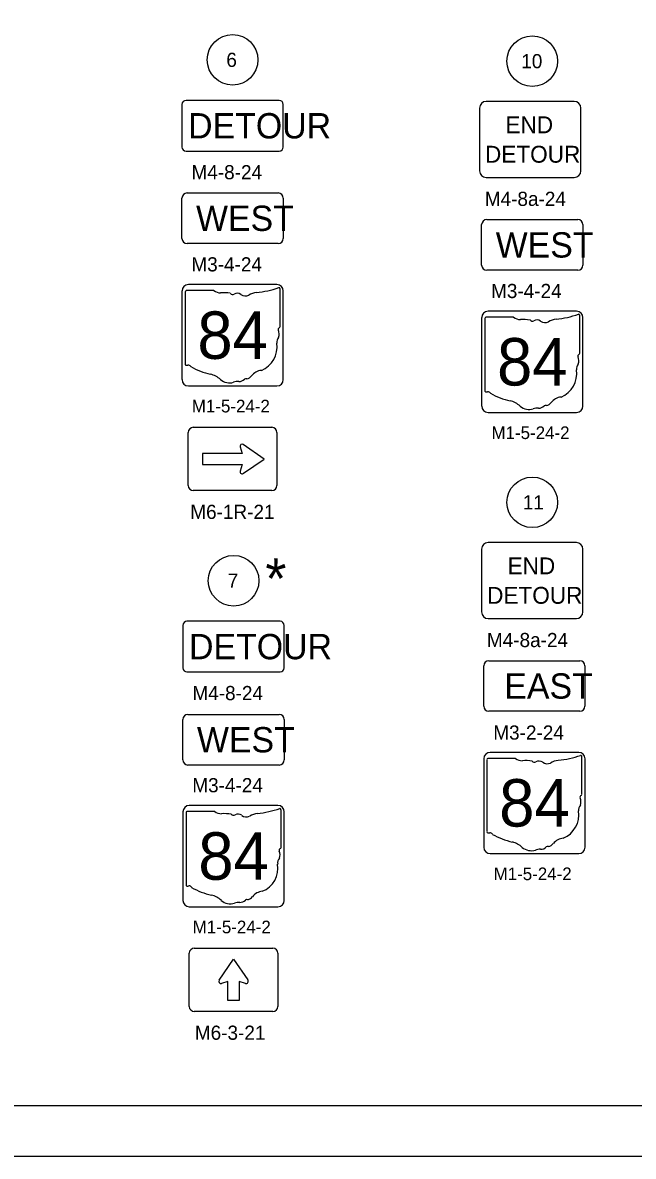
# Model space of a CAD drawing. Extents: x 0 to 54.8, y 0 to 22.
# Drawn here: x 21.94 to 27.97, y 0 to 11.2 of the extents above; entities that cross this region are included whole.
import ezdxf

# ---------------------------------------------------------------- set-up
doc = ezdxf.new("R2010")
doc.units = 0
for name, color, linetype in [('GM_X_County', 7, 'Continuous'), ('GM_X_County_Road', 7, 'Continuous'), ('GM_X_Minor_River_Text', 7, 'Continuous'), ('GM_X_Township', 7, 'Continuous')]:
    doc.layers.add(name, color=color, linetype=linetype)

msp = doc.modelspace()

# ---------------------------------------------------------------- linework, layer by layer
at = {"layer": 'GM_X_County'}
msp.add_lwpolyline([(0, 0), (34, 0), (34, 22), (0, 22)], close=True, dxfattribs=at)
at = {"layer": 'GM_X_County_Road'}
for centre in [(24.014, 10.831), (26.973, 10.818), (26.973, 6.46), (24.024, 5.686)]:
    msp.add_circle(centre, 0.25, dxfattribs=at)
at = {"layer": 'GM_X_Minor_River_Text'}
for p, q in [((23.514, 9.066), (23.514, 9.466)), ((23.564, 9.516), (24.464, 9.516)), ((24.514, 9.466), (24.514, 9.066)), ((26.473, 8.803), (26.473, 9.203)), ((26.523, 9.253), (27.423, 9.253)), ((27.473, 9.203), (27.473, 8.803)), ((24.464, 9.016), (23.564, 9.016)), ((27.423, 8.753), (26.523, 8.753)), ((23.545, 8.539), (23.545, 7.827)), ((23.829, 8.551), (23.554, 8.551)), ((24.482, 8.196), (24.482, 8.569)), ((26.788, 8.288), (26.513, 8.288)), ((27.441, 7.933), (27.441, 8.306)), ((24.482, 8.196), (24.482, 8.196)), ((26.504, 8.276), (26.504, 7.564)), ((27.441, 7.933), (27.441, 7.933)), ((23.626, 7.201), (24.401, 7.201)), ((23.576, 6.626), (23.576, 7.151)), ((24.451, 7.151), (24.451, 6.626)), ((24.108, 6.943), (23.717, 6.943)), ((23.717, 6.943), (23.717, 6.834)), ((24.088, 7.007), (24.108, 6.943)), ((24.326, 6.888), (24.119, 7.03)), ((23.717, 6.834), (24.108, 6.834)), ((24.108, 6.834), (24.088, 6.769)), ((24.122, 6.749), (24.326, 6.888)), ((24.401, 6.576), (23.626, 6.576)), ((26.493, 4.446), (26.493, 4.846)), ((26.543, 4.896), (27.443, 4.896)), ((27.493, 4.846), (27.493, 4.446)), ((27.443, 4.396), (26.543, 4.396)), ((23.523, 3.915), (23.523, 4.315)), ((23.573, 4.365), (24.473, 4.365)), ((24.523, 4.315), (24.523, 3.915)), ((26.808, 3.93), (26.534, 3.93)), ((27.462, 3.576), (27.462, 3.948)), ((24.473, 3.865), (23.573, 3.865)), ((26.525, 3.918), (26.525, 3.207)), ((27.462, 3.576), (27.462, 3.576)), ((23.554, 3.394), (23.554, 2.682)), ((23.838, 3.406), (23.563, 3.406)), ((24.492, 3.051), (24.492, 3.424)), ((24.492, 3.051), (24.492, 3.051)), ((23.636, 2.056), (24.411, 2.056)), ((23.586, 1.481), (23.586, 2.006)), ((23.881, 1.739), (24.023, 1.946)), ((24.023, 1.946), (24.163, 1.742)), ((24.461, 2.006), (24.461, 1.481)), ((23.968, 1.728), (23.904, 1.708)), ((23.968, 1.54), (23.968, 1.728)), ((24.142, 1.708), (24.078, 1.728)), ((24.078, 1.728), (24.078, 1.54)), ((24.078, 1.54), (23.968, 1.54)), ((24.411, 1.431), (23.636, 1.431))]:
    msp.add_line(p, q, dxfattribs=at)
for points in [[(24.474, 10.43), (23.554, 10.43)], [(27.388, 10.42), (26.518, 10.42)], [(23.514, 10.39), (23.514, 9.97)], [(24.514, 9.97), (24.514, 10.39)], [(26.453, 10.355), (26.453, 9.735)], [(27.453, 9.735), (27.453, 10.355)], [(23.554, 9.93), (24.474, 9.93)], [(26.518, 9.67), (27.388, 9.67)], [(23.514, 8.548), (23.514, 7.673)], [(24.452, 8.611), (23.577, 8.611)], [(24.514, 7.673), (24.514, 8.548)], [(27.411, 8.348), (26.536, 8.348)], [(26.473, 8.285), (26.473, 7.41)], [(27.473, 7.41), (27.473, 8.285)], [(23.577, 7.611), (24.452, 7.611)], [(26.536, 7.348), (27.411, 7.348)], [(27.408, 6.062), (26.538, 6.062)], [(26.473, 5.997), (26.473, 5.377)], [(27.473, 5.377), (27.473, 5.997)], [(24.483, 5.285), (23.563, 5.285)], [(26.538, 5.312), (27.408, 5.312)], [(23.523, 5.245), (23.523, 4.825)], [(24.523, 4.825), (24.523, 5.245)], [(23.563, 4.785), (24.483, 4.785)], [(26.494, 3.928), (26.494, 3.053)], [(27.432, 3.99), (26.557, 3.99)], [(27.494, 3.053), (27.494, 3.928)], [(23.524, 3.403), (23.524, 2.528)], [(24.461, 3.466), (23.586, 3.466)], [(24.524, 2.528), (24.524, 3.403)], [(26.557, 2.99), (27.432, 2.99)], [(23.586, 2.466), (24.461, 2.466)]]:
    msp.add_lwpolyline(points, dxfattribs=at)
for centre, radius, start, end in [((23.554, 10.39), 0.04, 90, 180), ((24.474, 10.39), 0.04, 0, 90), ((26.518, 10.355), 0.065, 90, 180), ((27.388, 10.355), 0.065, 0, 90), ((23.554, 9.97), 0.04, 180, 270), ((24.474, 9.97), 0.04, 270, 0), ((26.518, 9.735), 0.065, 180, 270), ((27.388, 9.735), 0.065, 270, 0), ((23.564, 9.466), 0.05, 90, 180), ((24.464, 9.466), 0.05, 0, 90), ((26.523, 9.203), 0.05, 90, 180), ((27.423, 9.203), 0.05, 0, 90), ((23.564, 9.066), 0.05, 180, 270), ((24.464, 9.066), 0.05, 270, 0), ((26.523, 8.803), 0.05, 180, 270), ((27.423, 8.803), 0.05, 270, 0), ((23.577, 8.548), 0.0625, 90, 180), ((23.556, 8.54), 0.0109, 98.1301, 188.1301), ((23.894, 8.634), 0.105, 231.6195, 271.1119), ((23.929, 8.152), 0.378, 80.4867, 94.9883), ((24.015, 8.544), 0.0304, 219.7921, 297.1024), ((24.059, 8.462), 0.0632, 54.4667, 119.1411), ((24.141, 8.574), 0.076, 233.8562, 294.8282), ((24.275, 8.334), 0.2, 97.3462, 120.7689), ((24.148, 9.521), 0.994, 275.8445, 288.9065), ((24.452, 8.548), 0.0625, 0, 90), ((24.472, 8.57), 0.0104, 351.8621, 97.738), ((26.536, 8.285), 0.0625, 90, 180), ((26.515, 8.277), 0.0109, 98.1301, 188.1301), ((26.853, 8.371), 0.105, 231.6195, 271.1119), ((27.107, 9.258), 0.994, 275.8445, 288.9065), ((27.411, 8.285), 0.0625, 0, 90), ((27.431, 8.307), 0.0104, 351.8621, 97.738), ((24.48, 8.169), 0.0162, 107.944, 210.337), ((24.471, 8.195), 0.0112, 289.6038, 7.7341), ((26.888, 7.888), 0.378, 80.4867, 94.9883), ((26.974, 8.281), 0.0304, 219.7921, 297.1024), ((27.018, 8.199), 0.0632, 54.4667, 119.1411), ((27.1, 8.311), 0.076, 233.8562, 294.8282), ((27.234, 8.071), 0.2, 97.3462, 120.7689), ((24.52, 8.041), 0.0705, 136.8065, 186.9296), ((24.377, 8.122), 0.097, 340.033, 23.6496), ((24.204, 7.993), 0.249, 292.3089, 8.9858), ((27.439, 7.906), 0.0162, 107.944, 210.337), ((27.336, 7.859), 0.097, 340.033, 23.6496), ((27.43, 7.932), 0.0112, 289.6038, 7.7341), ((23.556, 7.826), 0.011, 171.9584, 258.3066), ((23.557, 7.898), 0.0836, 267.339, 280.6039), ((23.574, 7.786), 0.0302, 29.7484, 93.2717), ((23.955, 8.425), 0.718, 240.4129, 257.1985), ((24.309, 7.627), 0.136, 94.4031, 142.5768), ((27.163, 7.73), 0.249, 292.3089, 8.9858), ((27.479, 7.778), 0.0705, 136.8065, 186.9296), ((23.577, 7.673), 0.0625, 180, 270), ((23.741, 7.508), 0.225, 47.1842, 75.836), ((23.984, 7.783), 0.143, 230.7004, 286.2918), ((24.066, 7.537), 0.117, 85.6951, 111.2099), ((24.077, 7.729), 0.0759, 268.777, 315.5493), ((24.146, 7.66), 0.0214, 65.7517, 132.6484), ((24.136, 7.758), 0.0803, 282.8732, 323.2771), ((24.452, 7.673), 0.0625, 270, 0), ((26.515, 7.563), 0.011, 171.9584, 258.3066), ((26.516, 7.635), 0.0836, 267.339, 280.6039), ((26.534, 7.523), 0.0302, 29.7484, 93.2717), ((26.914, 8.162), 0.718, 240.4129, 257.1985), ((26.536, 7.41), 0.0625, 180, 270), ((26.7, 7.245), 0.225, 47.1842, 75.836), ((26.943, 7.52), 0.143, 230.7004, 286.2918), ((27.036, 7.466), 0.0759, 268.777, 315.5493), ((27.105, 7.397), 0.0214, 65.7517, 132.6484), ((27.095, 7.495), 0.0803, 282.8732, 323.2771), ((27.268, 7.364), 0.136, 94.4031, 142.5768), ((27.411, 7.41), 0.0625, 270, 0), ((27.025, 7.274), 0.117, 85.6951, 111.2099), ((23.626, 7.151), 0.05, 90, 180), ((24.401, 7.151), 0.05, 0, 90), ((24.108, 7.013), 0.0209, 55.4112, 197.2046), ((24.108, 6.763), 0.0209, 162.7954, 315.0096), ((23.626, 6.626), 0.05, 180, 270), ((24.401, 6.626), 0.05, 270, 360), ((26.538, 5.997), 0.065, 90, 180), ((27.408, 5.997), 0.065, 0, 90), ((26.538, 5.377), 0.065, 180, 270), ((27.408, 5.377), 0.065, 270, 0), ((23.563, 5.245), 0.04, 90, 180), ((24.483, 5.245), 0.04, 0, 90), ((23.563, 4.825), 0.04, 180, 270), ((24.483, 4.825), 0.04, 270, 0), ((26.543, 4.846), 0.05, 90, 180), ((27.443, 4.846), 0.05, 0, 90), ((26.543, 4.446), 0.05, 180, 270), ((27.443, 4.446), 0.05, 270, 0), ((23.573, 4.315), 0.05, 90, 180), ((24.473, 4.315), 0.05, 0, 90), ((26.557, 3.928), 0.0625, 90, 180), ((26.535, 3.92), 0.0109, 98.1301, 188.1301), ((26.874, 4.013), 0.105, 231.6195, 271.1119), ((27.128, 4.901), 0.994, 275.8445, 288.9065), ((27.432, 3.928), 0.0625, 0, 90), ((27.452, 3.95), 0.0104, 351.8621, 97.738), ((23.573, 3.915), 0.05, 180, 270), ((24.473, 3.915), 0.05, 270, 0), ((26.909, 3.531), 0.378, 80.4867, 94.9883), ((26.995, 3.923), 0.0304, 219.7921, 297.1024), ((27.039, 3.841), 0.0632, 54.4667, 119.1411), ((27.121, 3.954), 0.076, 233.8562, 294.8282), ((27.255, 3.713), 0.2, 97.3462, 120.7689), ((27.46, 3.549), 0.0162, 107.944, 210.337), ((27.357, 3.501), 0.097, 340.033, 23.6496), ((27.451, 3.574), 0.0112, 289.6038, 7.7341), ((23.586, 3.403), 0.0625, 90, 180), ((23.565, 3.395), 0.0109, 98.1301, 188.1301), ((23.903, 3.489), 0.105, 231.6195, 271.1119), ((23.938, 3.007), 0.378, 80.4867, 94.9883), ((24.024, 3.399), 0.0304, 219.7921, 297.1024), ((24.069, 3.317), 0.0632, 54.4667, 119.1411), ((24.15, 3.429), 0.076, 233.8562, 294.8282), ((24.285, 3.189), 0.2, 97.3462, 120.7689), ((24.158, 4.376), 0.994, 275.8445, 288.9065), ((24.461, 3.403), 0.0625, 0, 90), ((24.481, 3.425), 0.0104, 351.8621, 97.738), ((27.184, 3.373), 0.249, 292.3089, 8.9858), ((27.499, 3.42), 0.0705, 136.8065, 186.9296), ((26.535, 3.205), 0.011, 171.9584, 258.3066), ((26.537, 3.278), 0.0836, 267.339, 280.6039), ((26.554, 3.166), 0.0302, 29.7484, 93.2717), ((26.935, 3.805), 0.718, 240.4129, 257.1985), ((27.289, 3.007), 0.136, 94.4031, 142.5768), ((24.489, 3.024), 0.0162, 107.944, 210.337), ((24.481, 3.05), 0.0112, 289.6038, 7.7341), ((26.557, 3.053), 0.0625, 180, 270), ((26.721, 2.887), 0.225, 47.1842, 75.836), ((26.964, 3.162), 0.143, 230.7004, 286.2918), ((27.046, 2.916), 0.117, 85.6951, 111.2099), ((27.057, 3.109), 0.0759, 268.777, 315.5493), ((27.125, 3.04), 0.0214, 65.7517, 132.6484), ((27.116, 3.138), 0.0803, 282.8732, 323.2771), ((27.432, 3.053), 0.0625, 270, 0), ((24.529, 2.896), 0.0705, 136.8065, 186.9296), ((24.386, 2.977), 0.097, 340.033, 23.6496), ((24.213, 2.848), 0.249, 292.3089, 8.9858), ((23.565, 2.681), 0.011, 171.9584, 258.3066), ((23.567, 2.753), 0.0836, 267.339, 280.6039), ((23.584, 2.641), 0.0302, 29.7484, 93.2717), ((23.964, 3.28), 0.718, 240.4129, 257.1985), ((23.75, 2.363), 0.225, 47.1842, 75.836), ((24.318, 2.482), 0.136, 94.4031, 142.5768), ((23.586, 2.528), 0.0625, 180, 270), ((23.993, 2.638), 0.143, 230.7004, 286.2918), ((24.076, 2.392), 0.117, 85.6951, 111.2099), ((24.086, 2.584), 0.0759, 268.777, 315.5493), ((24.155, 2.515), 0.0214, 65.7517, 132.6484), ((24.146, 2.613), 0.0803, 282.8732, 323.2771), ((24.461, 2.528), 0.0625, 270, 0), ((23.636, 2.006), 0.05, 90, 180), ((24.411, 2.006), 0.05, 0, 90), ((23.898, 1.728), 0.0209, 145.4112, 287.2046), ((24.148, 1.728), 0.0209, 252.7954, 45.0096), ((23.636, 1.481), 0.05, 180, 270), ((24.411, 1.481), 0.05, 270, 0)]:
    msp.add_arc(centre, radius, start, end, dxfattribs=at)
at = {"layer": 'GM_X_Township'}
msp.add_lwpolyline([(1.5, 21.5), (33.5, 21.5), (33.5, 0.5), (1.5, 0.5)], close=True, dxfattribs=at)

# ---------------------------------------------------------------- texts
at = {"layer": 'GM_X_County_Road'}
for s, height, p in [('6', 0.14, (23.952, 10.761)), ('10', 0.14, (26.864, 10.748)), ('M4-8-24', 0.14, (23.608, 9.651)), ('M4-8a-24', 0.14, (26.504, 9.388)), ('M3-4-24', 0.14, (23.607, 8.741)), ('M3-4-24', 0.14, (26.566, 8.478)), ('M1-5-24-2', 0.125, (23.611, 7.348)), ('M1-5-24-2', 0.125, (26.57, 7.085)), ('11', 0.14, (26.879, 6.39)), ('M6-1R-21', 0.14, (23.596, 6.296)), ('*', 0.4, (24.337, 5.507)), ('7', 0.14, (23.965, 5.616)), ('M4-8a-24', 0.14, (26.525, 5.03)), ('M4-8-24', 0.14, (23.617, 4.506)), ('M3-2-24', 0.14, (26.588, 4.116)), ('M3-4-24', 0.14, (23.616, 3.596)), ('M1-5-24-2', 0.125, (26.591, 2.728)), ('M1-5-24-2', 0.125, (23.62, 2.203)), ('M6-3-21', 0.14, (23.641, 1.151))]:
    msp.add_text(s, height=height, dxfattribs=at).set_placement(p)
at = {"layer": 'GM_X_Minor_River_Text'}
for s, height, p in [('DETOUR', 0.25, (23.575, 10.055)), ('END', 0.1667, (26.708, 10.106)), ('DETOUR', 0.1667, (26.506, 9.815)), ('WEST', 0.25, (23.653, 9.141)), ('WEST', 0.25, (26.612, 8.878)), ('84', 0.4688, (23.666, 7.877)), ('84', 0.4688, (26.625, 7.614)), ('END', 0.1667, (26.729, 5.749)), ('DETOUR', 0.1667, (26.527, 5.458)), ('DETOUR', 0.25, (23.584, 4.91)), ('EAST', 0.25, (26.697, 4.521)), ('WEST', 0.25, (23.662, 3.99)), ('84', 0.4688, (26.646, 3.257)), ('84', 0.4688, (23.675, 2.732))]:
    msp.add_text(s, height=height, dxfattribs=at).set_placement(p)

doc.saveas('drawing.dxf')
